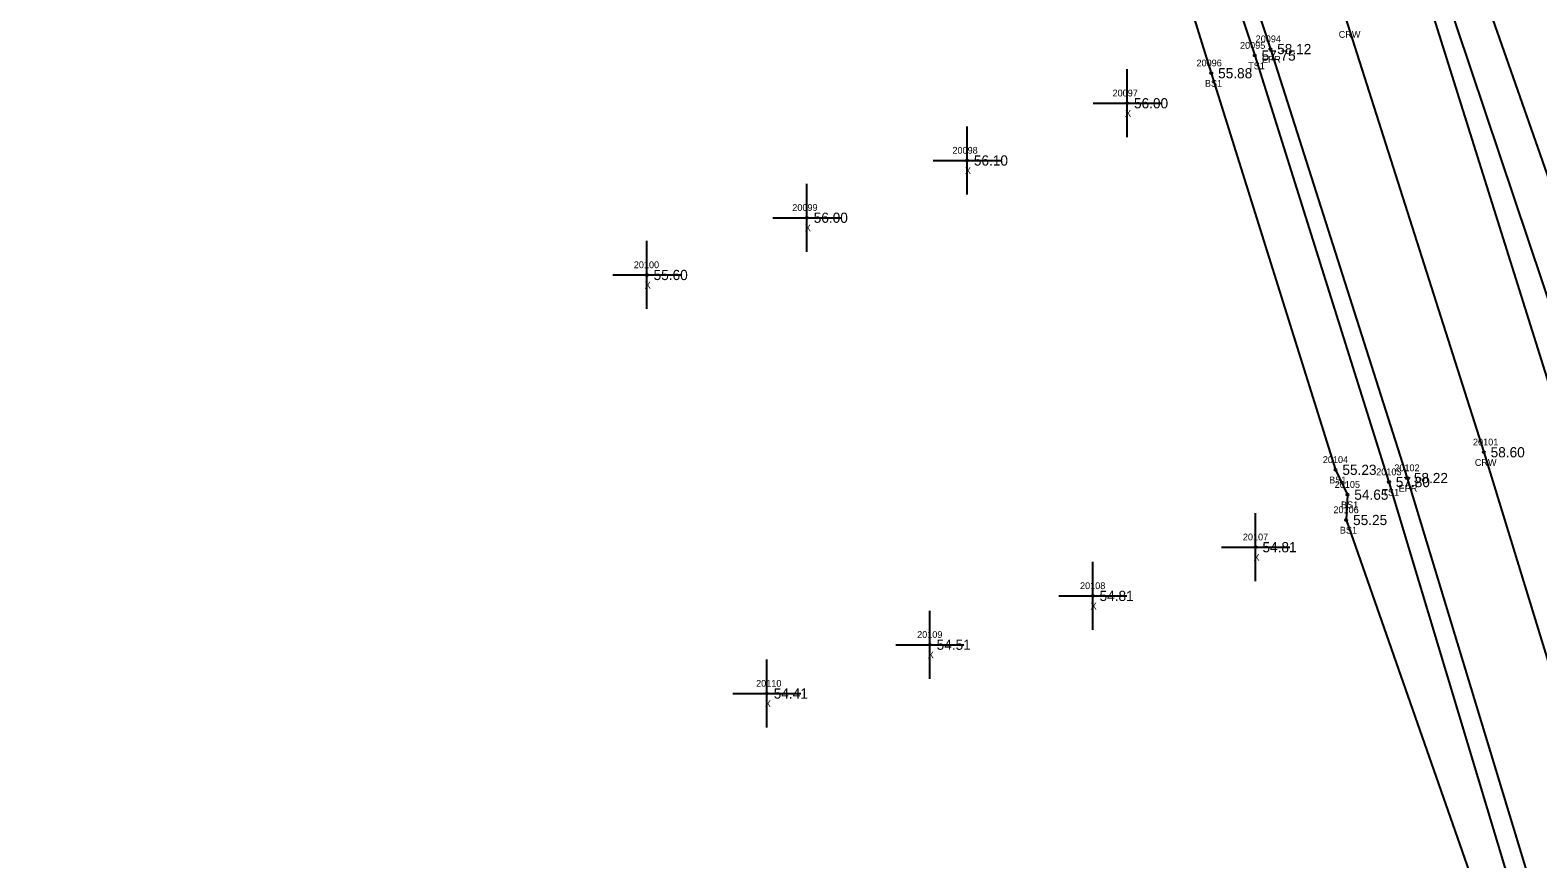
# Model space of a CAD drawing. Extents: x 2396547 to 2397655, y 770185 to 772649.
# Drawn here: x 2396658.8 to 2396880.4, y 771981.7 to 772103.6 of the extents above; entities that cross this region are included whole.
import ezdxf

# ---------------------------------------------------------------- set-up
doc = ezdxf.new("R2010")
doc.units = 0
for name, color, linetype in [('RD_DTM_BkLn1', 7, 'Continuous'), ('RD_DTM_BkLn2', 7, 'Continuous'), ('RD_DTM_BkLn_txCode', 7, 'Continuous'), ('RD_EX_Misc', 7, 'Continuous'), ('RD_EX_Misc_txCode', 7, 'Continuous'), ('RD_EX_Road', 7, 'Continuous'), ('RD_EX_Road_txCode', 7, 'Continuous'), ('RD_EX_TX_Misc_ELEV', 7, 'Continuous'), ('RD_EX_TX_Road_ELEV', 7, 'Continuous'), ('RD_HC_Survey_ELEV', 7, 'Continuous'), ('RD_HC_Survey_txCode', 7, 'Continuous'), ('RD_SMD_Locator', 7, 'Continuous')]:
    doc.layers.add(name, color=color, linetype=linetype)

msp = doc.modelspace()

# ---------------------------------------------------------------- linework, layer by layer
at = {"layer": 'RD_DTM_BkLn1'}
msp.add_lwpolyline([(2396669.86, 772614.94), (2396704.28, 772521.49), (2396739.29, 772426.89), (2396775.36, 772328.69), (2396800.21, 772259.35), (2396825.58, 772185.8), (2396852.46, 772104.52), (2396872.48, 772041.55), (2396897.57, 771959.72), (2396918.76, 771888.68), (2396939.09, 771818.34), (2396959.29, 771747.62), (2396993.72, 771617.68), (2397022.56, 771506.67), (2397049.1, 771404.69)], dxfattribs=at)
at = {"layer": 'RD_DTM_BkLn2'}
for points in [[(2396760.04, 772432.43), (2396789.87, 772348.56), (2396819.19, 772264.69), (2396848.46, 772183.36), (2396871.43, 772111.95), (2396893.38, 772049.37), (2396898.43, 772032.73), (2396909.27, 772037.73)], [(2396760.04, 772432.43), (2396760.2, 772413.09), (2396784.34, 772347.64), (2396814.22, 772264.11), (2396842.68, 772182.48), (2396866.31, 772110.61), (2396887.53, 772047.36), (2396893.79, 772029.88), (2396898.47, 772029.01), (2396909.27, 772037.73)], [(2396786.67, 772254.3), (2396812.18, 772180.2), (2396838.8, 772099.9), (2396858.54, 772037.17), (2396883.18, 771955.21), (2396904.21, 771884.05), (2396902.37, 771874.08)], [(2396781.71, 772252.52), (2396807.28, 772178.23), (2396832.42, 772097.31), (2396850.69, 772038.97), (2396852.44, 772035.31), (2396852.26, 772031.59), (2396879.38, 771953.92), (2396900.31, 771883.04), (2396902.37, 771874.08)]]:
    msp.add_lwpolyline(points, dxfattribs=at)
at = {"layer": 'RD_EX_Misc'}
for p, q in [((2396820.05, 772087.89), (2396820.05, 772097.89)), ((2396815.05, 772092.89), (2396825.05, 772092.89)), ((2396796.51, 772079.47), (2396796.51, 772089.47)), ((2396791.51, 772084.47), (2396801.51, 772084.47)), ((2396772.97, 772071.05), (2396772.97, 772081.05)), ((2396767.97, 772076.05), (2396777.97, 772076.05)), ((2396749.43, 772062.63), (2396749.43, 772072.63)), ((2396744.43, 772067.63), (2396754.43, 772067.63)), ((2396838.94, 772022.59), (2396838.94, 772032.59)), ((2396833.94, 772027.59), (2396843.94, 772027.59)), ((2396814.99, 772015.42), (2396814.99, 772025.42)), ((2396809.99, 772020.42), (2396819.99, 772020.42)), ((2396791.04, 772008.24), (2396791.04, 772018.24)), ((2396786.04, 772013.24), (2396796.04, 772013.24)), ((2396767.09, 772001.06), (2396767.09, 772011.06)), ((2396762.09, 772006.06), (2396772.09, 772006.06))]:
    msp.add_line(p, q, dxfattribs=at)
at = {"layer": 'RD_EX_Road'}
for points in [[(2396680.92, 772617.84), (2396715.6, 772525.73), (2396750.68, 772430.62), (2396786.3, 772332.21), (2396811.38, 772263.31), (2396839.69, 772181.74), (2396863.75, 772109.83), (2396883.63, 772046.56), (2396889.54, 772027.11), (2396896.25, 772004.37), (2396904.34, 771978.33), (2396908.24, 771964.89), (2396921.74, 771919.68), (2396927.03, 771902.11), (2396950.2, 771821.74), (2396970.47, 771750.68), (2396978.33, 771721.29), (2396990.58, 771675.04), (2397004.94, 771620.49), (2397034.26, 771508.8), (2397061.11, 771410.49), (2397060.64, 771407.04), (2397062.07, 771407.67)], [(2396658.78, 772611.07), (2396693.37, 772516.9), (2396729.65, 772418.78), (2396760.7, 772333.11), (2396788.58, 772254.87), (2396814.65, 772181.57), (2396841.1, 772100.86), (2396861.19, 772037.76), (2396886.09, 771955.71), (2396907.15, 771884.49), (2396928.56, 771811.72), (2396947.65, 771744.09), (2396985.17, 771602.64), (2397011.11, 771504.04), (2397037.95, 771404.25), (2397039, 771401.22)]]:
    msp.add_lwpolyline(points, dxfattribs=at)
at = {"layer": 'RD_SMD_Locator'}
for centre in [(2396841.1, 772100.86), (2396838.8, 772099.9), (2396832.42, 772097.31), (2396820.05, 772092.89), (2396796.51, 772084.47), (2396772.97, 772076.05), (2396749.43, 772067.63), (2396872.48, 772041.55), (2396850.69, 772038.97), (2396858.54, 772037.17), (2396861.19, 772037.76), (2396852.44, 772035.31), (2396852.26, 772031.59), (2396838.94, 772027.59), (2396814.99, 772020.42), (2396791.04, 772013.24), (2396767.09, 772006.06)]:
    msp.add_circle(centre, 0.15, dxfattribs=at)

# ---------------------------------------------------------------- texts
at = {"layer": 'RD_DTM_BkLn_txCode'}
for s, p in [('20095', (2396836.64, 772100.9)), ('20096', (2396830.24, 772098.31)), ('TS1', (2396837.84, 772097.9)), ('BS1', (2396831.48, 772095.31)), ('20104', (2396848.81, 772039.97)), ('20103', (2396856.66, 772038.17)), ('BS1', (2396849.74, 772036.97)), ('20105', (2396850.56, 772036.31)), ('TS1', (2396857.58, 772035.17)), ('BS1', (2396851.49, 772033.31)), ('20106', (2396850.37, 772032.59)), ('BS1', (2396851.32, 772029.59))]:
    msp.add_text(s, height=1, dxfattribs=at).set_placement(p)
at = {"layer": 'RD_EX_Misc_txCode'}
for s, p in [('20097', (2396817.9, 772093.89)), ('X', (2396819.74, 772090.89)), ('20098', (2396794.36, 772085.47)), ('X', (2396796.2, 772082.47)), ('20099', (2396770.82, 772077.05)), ('X', (2396772.66, 772074.05)), ('20100', (2396747.52, 772068.63)), ('X', (2396749.12, 772065.63)), ('20107', (2396837.06, 772028.59)), ('X', (2396838.62, 772025.59)), ('20108', (2396813.12, 772021.42)), ('X', (2396814.67, 772018.42)), ('20109', (2396789.17, 772014.24)), ('X', (2396790.73, 772011.24)), ('20110', (2396765.5, 772007.06)), ('X', (2396766.78, 772004.06))]:
    msp.add_text(s, height=1, dxfattribs=at).set_placement(p)
at = {"layer": 'RD_EX_Road_txCode'}
for s, p in [('20094', (2396838.94, 772101.86)), ('EPR', (2396839.87, 772098.86)), ('20102', (2396859.32, 772038.76)), ('EPR', (2396859.96, 772035.76))]:
    msp.add_text(s, height=1, dxfattribs=at).set_placement(p)
at = {"layer": 'RD_EX_TX_Misc_ELEV'}
for s, p in [('57.75', (2396839.8, 772099.15)), ('55.88', (2396833.42, 772096.56)), ('56.00', (2396821.05, 772092.14)), ('56.10', (2396797.51, 772083.72)), ('56.00', (2396773.97, 772075.3)), ('55.60', (2396750.43, 772066.88)), ('55.23', (2396851.69, 772038.22)), ('54.65', (2396853.44, 772034.56)), ('57.80', (2396859.54, 772036.42)), ('55.25', (2396853.26, 772030.84)), ('54.81', (2396839.94, 772026.84)), ('54.81', (2396815.99, 772019.67)), ('54.51', (2396792.04, 772012.49)), ('54.41', (2396768.09, 772005.31))]:
    msp.add_text(s, height=1.5, dxfattribs=at).set_placement(p)
at = {"layer": 'RD_EX_TX_Road_ELEV'}
for s, p in [('58.12', (2396842.1, 772100.11)), ('58.22', (2396862.19, 772037.01))]:
    msp.add_text(s, height=1.5, dxfattribs=at).set_placement(p)
at = {"layer": 'RD_HC_Survey_ELEV'}
msp.add_text('58.60', height=1.5, dxfattribs=at).set_placement((2396873.48, 772040.8))
at = {"layer": 'RD_HC_Survey_txCode'}
for s, p in [('CRW', (2396851.15, 772102.52)), ('20101', (2396870.89, 772042.55)), ('CRW', (2396871.16, 772039.55))]:
    msp.add_text(s, height=1, dxfattribs=at).set_placement(p)

doc.saveas('drawing.dxf')
